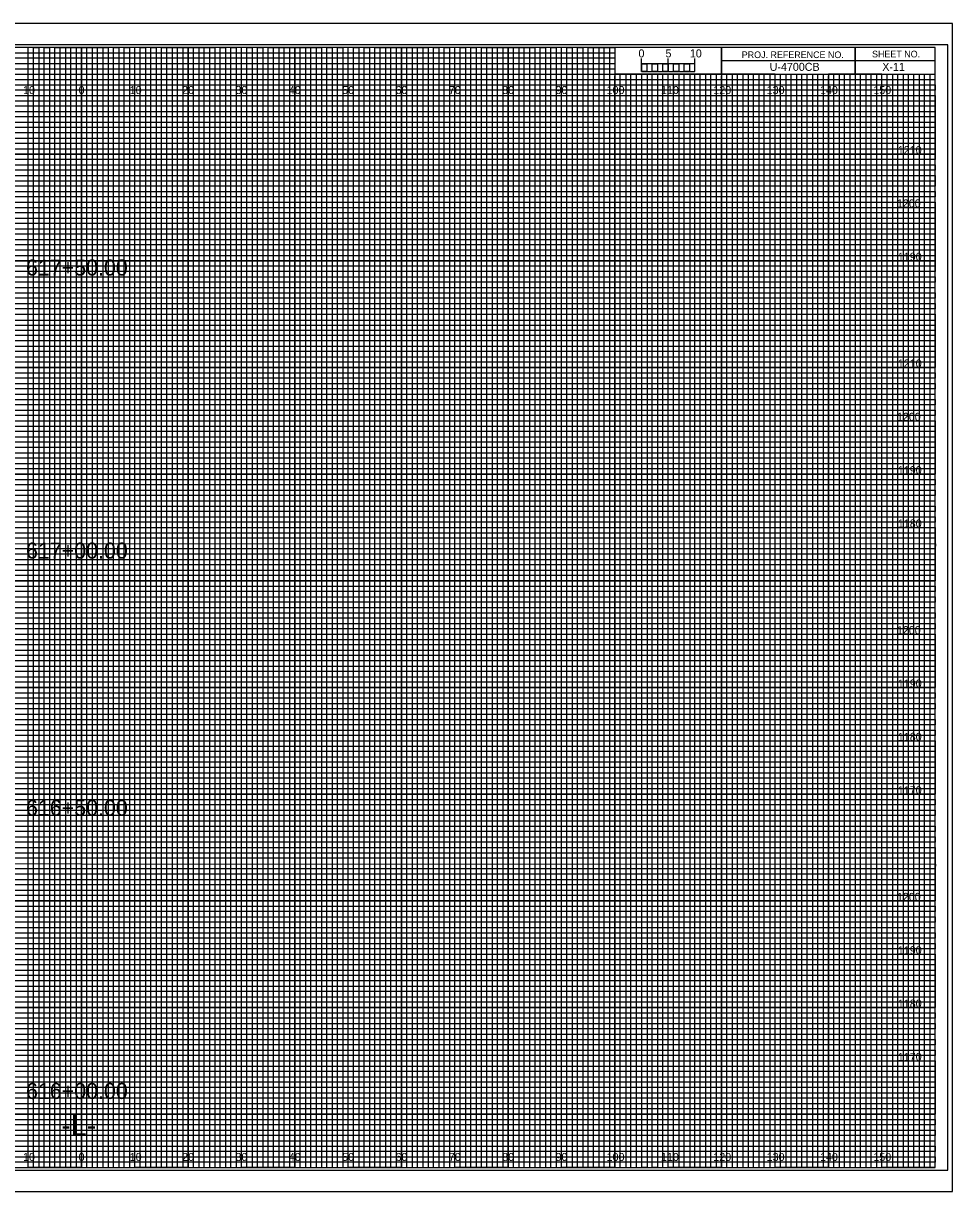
# Model space of a CAD drawing. Extents: x -13 to 323, y 1976 to 2194.
# Drawn here: x 149.1 to 323.3, y 1975.5 to 2194.5 of the extents above; entities that cross this region are included whole.
import ezdxf

# ---------------------------------------------------------------- set-up
doc = ezdxf.new("R2010")
doc.units = 0
for name, color, linetype in [('Prop XS Alignment Label', 7, 'Continuous'), ('Prop XS Bar Scale Labels', 7, 'Continuous'), ('Prop XS Elevation Labels', 7, 'Continuous'), ('Prop XS Offset Labels', 7, 'Continuous'), ('Prop XS Project Number', 7, 'Continuous'), ('Prop XS Sheet Number', 7, 'Continuous'), ('Prop XS Station Labels', 7, 'Continuous'), ('Sheet Cross Section CELL', 7, 'Continuous'), ('Sheet Cross Section Grid Major CELL', 7, 'Continuous'), ('Sheet Cross Section Grid Middle CELL', 7, 'Continuous'), ('Sheet Cross Section Grid Minor 1 CELL', 7, 'Continuous'), ('Sheet Cross Section Grid Minor 2 CELL', 7, 'Continuous'), ('Sheet Cross Section Scale CELL', 7, 'Continuous'), ('Sheet Cutting Line CELL', 7, 'Continuous'), ('Sheet DOT Grid CELL', 7, 'Continuous'), ('Sheet Plot Border Inside CELL', 7, 'Continuous'), ('Sheet Plot Border Outside CELL', 7, 'Continuous')]:
    doc.layers.add(name, color=color, linetype=linetype)

msp = doc.modelspace()

# ---------------------------------------------------------------- linework, layer by layer
at = {"layer": 'Sheet Cross Section CELL'}
for p, q in [((305, 2190), (305, 2185)), ((305, 2185), (305, 2190)), ((280, 2187.5), (280, 2185)), ((320, 2187.49), (280, 2187.49)), ((280, 2185), (320, 2185))]:
    msp.add_line(p, q, dxfattribs=at)
for points in [[(320, 2190), (0, 2190), (0, 1980), (320, 1980)], [(280, 2190), (260, 2190), (260, 2185.03), (280, 2185.03)], [(320, 2190), (280, 2190), (280, 2185), (320, 2185)]]:
    msp.add_lwpolyline(points, close=True, dxfattribs=at)
at = {"layer": 'Sheet Cross Section Grid Major CELL'}
for p, q in [((150, 2190), (140, 2190)), ((150, 1980), (150, 2190)), ((170, 2190), (160, 2190)), ((160, 2190), (160, 1980)), ((170, 1980), (170, 2190)), ((190, 2190), (180, 2190)), ((180, 2190), (180, 1980)), ((190, 1980), (190, 2190)), ((210, 2190), (200, 2190)), ((200, 2190), (200, 1980)), ((210, 1980), (210, 2190)), ((230, 2190), (220, 2190)), ((220, 2190), (220, 1980)), ((230, 1980), (230, 2190)), ((250, 2190), (240, 2190)), ((240, 2190), (240, 1980)), ((250, 1980), (250, 2190)), ((260, 2190), (260, 1980)), ((270, 1980), (270, 2185)), ((290, 2185), (280, 2185)), ((280, 2185), (280, 1980)), ((290, 1980), (290, 2185)), ((310, 2185), (300, 2185)), ((300, 2185), (300, 1980)), ((310, 1980), (310, 2185)), ((160, 1980), (150, 1980)), ((180, 1980), (170, 1980)), ((200, 1980), (190, 1980)), ((220, 1980), (210, 1980)), ((240, 1980), (230, 1980)), ((260, 1980), (250, 1980)), ((280, 1980), (270, 1980)), ((300, 1980), (290, 1980)), ((320, 1980), (310, 1980)), ((320, 1980), (320, 1980))]:
    msp.add_line(p, q, dxfattribs=at)
for points in [[(0, 2180), (320, 2180), (320, 2170), (0, 2170)], [(0, 2160), (320, 2160), (320, 2150), (0, 2150)], [(0, 2140), (320, 2140), (320, 2130), (0, 2130)], [(0, 2120), (320, 2120), (320, 2110), (0, 2110)], [(0, 2100), (320, 2100), (320, 2090), (0, 2090)], [(0, 2080), (320, 2080), (320, 2070), (0, 2070)], [(0, 2060), (320, 2060), (320, 2050), (0, 2050)], [(0, 2040), (320, 2040), (320, 2030), (0, 2030)], [(0, 2020), (320, 2020), (320, 2010), (0, 2010)], [(0, 2000), (320, 2000), (320, 1990), (0, 1990)]]:
    msp.add_lwpolyline(points, dxfattribs=at)
at = {"layer": 'Sheet Cross Section Grid Middle CELL'}
for points in [[(145, 1980), (155, 1980), (155, 2190), (165, 2190), (165, 1980), (175, 1980), (175, 2190), (185, 2190), (185, 1980), (195, 1980), (195, 2190), (205, 2190), (205, 1980), (215, 1980), (215, 2190), (225, 2190), (225, 1980), (235, 1980), (235, 2190), (245, 2190), (245, 1980), (255, 1980), (255, 2190), (259.93, 2190), (260, 2190), (260, 2185), (264.99, 2185), (264.99, 1980), (275, 1980), (275, 2185), (285, 2185), (285, 1980), (295, 1980), (295, 2185), (305, 2185), (305, 1980), (315, 1980), (315, 2185)], [(0, 2185), (275, 2185)], [(0, 2165), (320, 2165), (320, 2175), (0, 2175)], [(0, 2145), (320, 2145), (320, 2155), (0, 2155)], [(0, 2125), (320, 2125), (320, 2135), (0, 2135)], [(0, 2105), (320, 2105), (320, 2115), (0, 2115)], [(0, 2085), (320, 2085), (320, 2095), (0, 2095)], [(0, 2065), (320, 2065), (320, 2075), (0, 2075)], [(0, 2045), (320, 2045), (320, 2055), (0, 2055)], [(0, 2025), (320, 2025), (320, 2035), (0, 2035)], [(0, 2005), (320, 2005), (320, 2015), (0, 2015)], [(0, 1985), (320, 1985), (320, 1995), (0, 1995)]]:
    msp.add_lwpolyline(points, dxfattribs=at)
at = {"layer": 'Sheet Cross Section Grid Minor 1 CELL'}
for p, q in [((0, 2189), (260, 2189)), ((260, 2187.98), (0, 2187.98)), ((260, 2189), (260, 2187.98)), ((0, 2187), (260, 2187)), ((260, 2185.89), (0, 2185.89)), ((260, 2187), (260, 2185.89)), ((0, 2184), (320, 2184))]:
    msp.add_line(p, q, dxfattribs=at)
for points in [[(0, 2183), (270, 2183), (320, 2183), (320, 2182), (0, 2182)], [(0, 2181), (320, 2181), (320, 2179), (0, 2179)], [(0, 2178), (320, 2178), (320, 2177), (0, 2176.98)], [(0, 2176), (320, 2176), (320, 2174), (0, 2174)], [(0, 2173), (320, 2173), (320, 2172), (0, 2172)], [(0, 2171), (320, 2171), (320, 2169), (0, 2169)], [(0, 2168), (320, 2168), (320, 2167), (0, 2167)], [(0, 2166), (320, 2166), (320, 2164), (0, 2164)], [(0, 2163), (320, 2163), (320, 2162), (0, 2162)], [(0, 2161), (320, 2161), (320, 2159), (0, 2159)], [(0, 2158), (320, 2158), (320, 2157), (0, 2157)], [(0, 2156), (320, 2156), (320, 2153.95), (320, 2153), (320, 2152), (0, 2152)], [(0, 2154), (320, 2154), (320, 2153), (0, 2153)], [(0, 2151), (320, 2151), (320, 2149), (0, 2149.03)], [(0, 2149.03), (320, 2149), (320, 2148), (0, 2148)], [(0, 2147), (320, 2147), (320, 2146), (0, 2146)], [(0, 2144), (320, 2144), (320, 2143), (0, 2143)], [(0, 2142), (320, 2142), (320, 2141), (0, 2141)], [(-0.07, 2138.89), (320, 2138.89), (320, 2137.88), (-0.07, 2137.88)], [(0, 2137), (320, 2137), (320, 2136), (0, 2136)], [(0, 2134), (320, 2134), (320, 2133), (0, 2133)], [(0, 2132), (320, 2132), (320, 2131), (0, 2131)], [(0, 2129), (320, 2129), (320, 2128), (0, 2128)], [(0, 2127), (320, 2127), (320, 2126), (0, 2126)], [(0, 2124), (320, 2124), (320, 2123), (0, 2123)], [(0, 2122), (320, 2122), (320, 2121), (0, 2121)], [(0, 2119), (320, 2119), (319.99, 2117.98), (0, 2118)], [(0, 2117), (320, 2117), (320, 2116), (0, 2116)], [(0, 2114), (320, 2114), (320, 2113), (0, 2113)], [(0, 2112), (320, 2112), (320, 2111), (0, 2111)], [(0, 2109), (320, 2109), (320, 2108), (0, 2108)], [(0, 2107), (320, 2107), (320, 2106), (0, 2106)], [(0, 2104), (320, 2104), (320, 2103), (0, 2103)], [(0, 2102), (320, 2102), (320, 2101), (0, 2101)], [(0, 2099), (320, 2099), (320, 2098), (0, 2098)], [(0, 2096.99), (320.07, 2096.91), (320, 2096), (0, 2096)], [(0, 2094), (320, 2094), (320, 2093), (0, 2093)], [(0, 2092), (320, 2092), (320, 2091), (0, 2091)], [(0, 2089), (320, 2089), (320, 2088), (0, 2088)], [(0, 2087), (320, 2087), (320, 2086), (0, 2086)], [(0, 2084), (320, 2084), (320, 2083), (0, 2083)], [(0, 2082), (320, 2082), (320, 2081), (0, 2081)], [(0, 2079), (320, 2079), (320, 2078), (0, 2078)], [(0, 2077), (320, 2077), (320, 2076), (0, 2076)], [(0, 2074), (320, 2074), (320, 2073), (0, 2073)], [(0, 2072), (320, 2072), (320, 2071), (0, 2071)], [(0, 2069), (320, 2069), (320, 2068), (0, 2068)], [(0, 2067), (320, 2067), (320, 2066), (0, 2066)], [(0, 2064), (320, 2064), (320, 2063), (0, 2063)], [(0, 2062), (320, 2062), (320, 2061), (0, 2061)], [(0, 2059), (320, 2059), (319.99, 2057.98), (0, 2058)], [(0, 2057), (320, 2057), (320, 2056), (0, 2056)], [(0, 2054), (320, 2054), (320, 2053), (0, 2053)], [(0, 2052), (320, 2052), (320, 2051), (0, 2051)], [(0, 2049), (320, 2049), (320, 2048), (0, 2048)], [(0, 2047), (320, 2047), (320, 2046), (0, 2046)], [(0, 2044), (320, 2044), (320, 2043), (0, 2043)], [(0, 2042), (320, 2042), (320, 2041), (0, 2041)], [(0, 2039), (320, 2039), (320, 2038), (0, 2038)], [(0, 2036.99), (320.07, 2036.91), (320, 2036), (0, 2036)], [(0, 2034), (320, 2034), (320, 2033), (0, 2033)], [(0, 2032), (320, 2032), (320, 2031), (0, 2031)], [(0, 2029), (320, 2029), (320, 2028), (0, 2028)], [(0, 2027), (320, 2027), (320, 2026), (0, 2026)], [(0, 2024), (320, 2024), (320, 2023), (0, 2023)], [(0, 2022), (320, 2022), (320, 2021), (0, 2021)], [(0, 2019), (320, 2019), (320, 2018), (0, 2018)], [(0, 2017), (320, 2017), (320, 2016), (0, 2016)], [(0, 2014), (320, 2014), (320, 2013), (0, 2013)], [(0, 2012), (320, 2012), (320, 2011), (0, 2011)], [(0, 2009), (320, 2009), (320, 2008), (0, 2008)], [(0, 2007), (320, 2007), (320, 2006), (0, 2006)], [(0, 2004), (320, 2004), (320, 2003), (0, 2003)], [(0, 2002), (320, 2002), (320, 2001), (0, 2001)], [(0, 1999), (320, 1999), (320, 1998), (0, 1998)], [(0, 1997), (320, 1997), (320, 1996), (0, 1996)], [(0, 1994), (320, 1994), (320, 1993), (0, 1993)], [(0, 1992), (320, 1992), (320, 1991), (0, 1991)], [(0, 1989), (320, 1989), (320, 1988), (0, 1988)], [(0, 1987), (320, 1987), (320, 1986), (0, 1986)], [(0, 1984), (320, 1984), (320, 1983), (0, 1983)], [(0, 1982), (320, 1982), (320, 1981), (0, 1981)]]:
    msp.add_lwpolyline(points, dxfattribs=at)
at = {"layer": 'Sheet Cross Section Grid Minor 2 CELL'}
for p, q in [((267, 2185), (266.01, 2185)), ((266.01, 2185), (266.01, 1980)), ((267, 1980), (267, 2185)), ((269, 2185), (268, 2185)), ((268, 2185), (268, 1980)), ((269, 1980), (269, 2185)), ((266.01, 1980), (265, 1980)), ((268, 1980), (267, 1980))]:
    msp.add_line(p, q, dxfattribs=at)
for points in [[(150, 1980), (151, 1980), (151, 2190), (152, 2190), (152, 1980)], [(152, 1980), (153, 1980), (153, 2190), (154, 2190), (154, 1980)], [(155, 1980), (156, 1980), (156, 2190), (157, 2190), (157, 1980)], [(157, 1980), (158, 1980), (158, 2190), (159, 2190), (159, 1980)], [(160, 1980), (161, 1980), (161, 2190), (162, 2190), (162, 1980)], [(162, 1980), (163, 1980), (163, 2190), (164, 2190), (164, 1980)], [(165, 1980), (166, 1980), (166, 2190), (167, 2190), (167, 1980)], [(167, 1980), (168, 1980), (168, 2190), (169, 2190), (169, 1980)], [(170, 1980), (171, 1980), (171, 2190), (172, 2190), (172, 1980)], [(172, 1980), (173, 1980), (173, 2190), (174, 2190), (174, 1980)], [(175, 1980), (176, 1980), (176, 2190), (177, 2190), (177, 1980)], [(177, 1980), (178, 1980), (178, 2190), (179, 2190), (179, 1980)], [(180, 1980), (181, 1980), (181, 2190), (182, 2190), (182, 1980)], [(182, 1980), (183, 1980), (183, 2190), (184, 2190), (184, 1980)], [(185, 1980), (186, 1980), (186, 2190), (187, 2190), (187, 1980)], [(187, 1980), (188, 1980), (188, 2190), (189, 2190), (189, 1980)], [(190, 1980), (191, 1980), (191, 2190), (192, 2190), (192, 1980)], [(192, 1980), (193, 1980), (193, 2190), (194, 2190), (194, 1980)], [(195, 1980), (196, 1980), (196, 2190), (197, 2190), (197, 1980)], [(197, 1980), (198, 1980), (198, 2190), (199, 2190), (199, 1980)], [(200, 1980), (201, 1980), (201, 2190), (202, 2190), (202, 1980)], [(202, 1980), (203, 1980), (203, 2190), (204, 2190), (204, 1980)], [(205, 1980), (206, 1980), (206, 2190), (207, 2190), (207, 1980)], [(207, 1980), (208, 1980), (208, 2190), (209, 2190), (209, 1980)], [(210, 1980), (211, 1980), (211, 2190), (212, 2190), (212, 1980)], [(212, 1980), (213, 1980), (213, 2190), (214, 2190), (214, 1980)], [(215, 1980), (216, 1980), (216, 2190), (217, 2190), (217, 1980)], [(217, 1980), (218, 1980), (218, 2190), (219, 2190), (219, 1980)], [(220, 1980), (221, 1980), (221, 2190), (222, 2190), (222, 1980)], [(222, 1980), (223, 1980), (223, 2190), (224, 2190), (224, 1980)], [(225, 1980), (226, 1980), (226, 2190), (227, 2190), (227, 1980)], [(227, 1980), (228, 1980), (228, 2190), (229, 2190), (229, 1980)], [(230, 1980), (231, 1980), (231, 2190), (232, 2190), (232, 1980)], [(232, 1980), (233, 1980), (233, 2190), (234, 2190), (234, 1980)], [(235, 1980), (236, 1980), (236, 2190), (237, 2190), (237, 1980)], [(237, 1980), (238, 1980), (238, 2190), (239, 2190), (239, 1980)], [(240, 1980), (241, 1980), (241, 2190), (242, 2190), (242, 1980)], [(242, 1980), (243, 1980), (243, 2190), (244, 2190), (244, 1980)], [(245, 1980), (246, 1980), (246, 2190), (247, 2190), (247, 1980)], [(247, 1980), (248, 1980), (248, 2190), (249, 2190), (249, 1980)], [(250, 1980), (251, 1980), (251, 2190), (252, 2190), (252, 1980)], [(252, 1980), (253, 1980), (253, 2190), (254, 2190), (254, 1980)], [(255, 1980), (256, 1980), (256, 2190), (257, 2190), (257, 1980)], [(257, 1980), (258, 1980), (258, 2190), (259, 2190), (259, 1980)], [(260, 1980), (261, 1980), (261, 2185), (262.02, 2185), (262.02, 1980)], [(262, 1980), (263, 1980), (263, 2185), (263.99, 2185), (263.99, 1980)], [(270, 1980), (270.98, 1980), (270.98, 2185), (272, 2185), (272, 1980)], [(272, 1980), (273, 1980), (273, 2185), (274.05, 2185), (274.05, 1980)], [(275, 1980), (276, 1980), (276, 2185), (277, 2185), (277, 1980)], [(277, 1980), (278, 1980), (278, 2185), (279, 2185), (279, 1980)], [(280, 1980), (281, 1980), (281, 2185), (282, 2185), (282, 1980)], [(282, 1980), (283, 1980), (283, 2185), (284, 2185), (284, 1980)], [(285, 1980), (286, 1980), (286, 2185), (287, 2185), (287, 1980)], [(287, 1980), (288, 1980), (288, 2185), (289, 2185), (289, 1980)], [(290, 1980), (291, 1980), (291, 2185), (292, 2185), (292, 1980)], [(292, 1980), (293, 1980), (293, 2185), (294, 2185), (294, 1980)], [(295, 1980), (296, 1980), (296, 2185), (297, 2185), (297, 1980)], [(297, 1980), (298, 1980), (298, 2185), (299, 2185), (299, 1980)], [(300, 1980), (301, 1980), (301, 2185), (302, 2185), (302, 1980)], [(302, 1980), (303, 1980), (303, 2185), (304, 2185), (304, 1980)], [(305, 1980), (306, 1980), (306, 2185), (307, 2185), (307, 1980)], [(307, 1980), (308, 1980), (308, 2185), (309, 2185), (309, 1980)], [(310, 1980), (311, 1980), (311, 2185), (312, 2185), (312, 1980)], [(312, 1980), (313, 1980), (313, 2185), (314, 2185), (314, 1980)], [(315, 1980), (316, 1980), (316, 2185), (317, 2185), (317, 1980)], [(317, 1980), (318, 1980), (318, 2185), (319, 2185), (319, 1980)]]:
    msp.add_lwpolyline(points, dxfattribs=at)
at = {"layer": 'Sheet Cross Section Scale CELL'}
for p, q in [((265, 2185.49), (265, 2187.9)), ((265, 2186.9), (265, 2187.9)), ((270, 2185.49), (270, 2187.9)), ((275, 2185.49), (275, 2187.9)), ((275, 2186.9), (275, 2187.9))]:
    msp.add_line(p, q, dxfattribs=at)
for points in [[(275, 2186.9), (265, 2186.9), (265, 2185.49), (275, 2185.49)], [(265, 2186.9), (266, 2186.9), (266, 2185.49), (265, 2185.49)], [(267, 2186.9), (268, 2186.9), (268, 2185.49), (267, 2185.49)], [(269, 2186.9), (270, 2186.9), (270, 2185.49), (269, 2185.49)], [(271, 2186.9), (272, 2186.9), (272, 2185.49), (271, 2185.49)], [(273, 2186.9), (274, 2186.9), (274, 2185.49), (273, 2185.49)]]:
    msp.add_lwpolyline(points, close=True, dxfattribs=at)
at = {"layer": 'Sheet Cutting Line CELL'}
for p, q in [((323.3, 2194.5), (-13.4, 2194.5)), ((-13.4, 1975.5), (323.3, 1975.5))]:
    msp.add_line(p, q, dxfattribs=at)
at = {"layer": 'Sheet DOT Grid CELL'}
for p, q in [((150, 1980), (150, 2190)), ((160, 1980), (160, 2190)), ((170, 1980), (170, 2190)), ((180, 1980), (180, 2190)), ((190, 1980), (190, 2190)), ((200, 1980), (200, 2190)), ((210, 1980), (210, 2190)), ((220, 1980), (220, 2190)), ((230, 1980), (230, 2190)), ((240, 1980), (240, 2190)), ((250, 1980), (250, 2190)), ((260, 1980), (260, 2184.69)), ((270, 1980), (270, 2184.69)), ((280, 1980), (280, 2184.69)), ((290, 1980), (290, 2184.69)), ((300, 1980), (300, 2184.69)), ((310, 1980), (310, 2184.69)), ((0, 2180), (320, 2180)), ((0, 2170), (320, 2170)), ((0, 2160), (320, 2160)), ((0, 2150), (320, 2150)), ((0, 2140), (320, 2140)), ((0, 2130), (320, 2130)), ((0, 2120), (320, 2120)), ((0, 2110), (320, 2110)), ((0, 2100), (320, 2100)), ((0, 2090), (320, 2090)), ((0, 2080), (320, 2080)), ((0, 2070), (320, 2070)), ((0, 2060), (320, 2060)), ((0, 2050), (320, 2050)), ((0, 2040), (320, 2040)), ((0, 2030), (320, 2030)), ((0, 2020), (320, 2020)), ((0, 2010), (320, 2010)), ((0, 2000), (320, 2000)), ((0, 1990), (320, 1990))]:
    msp.add_line(p, q, dxfattribs=at)
at = {"layer": 'Sheet Plot Border Inside CELL'}
msp.add_lwpolyline([(-10.8, 1979.5), (322.4, 1979.5), (322.4, 2190.5), (-10.8, 2190.5)], close=True, dxfattribs=at)
at = {"layer": 'Sheet Plot Border Outside CELL'}
msp.add_lwpolyline([(-13.4, 1975.5), (323.3, 1975.5), (323.3, 2194.5), (-13.4, 2194.5)], close=True, dxfattribs=at)

# ---------------------------------------------------------------- texts
at = {"layer": 'Prop XS Alignment Label'}
msp.add_text('-L-', height=4, dxfattribs=at).set_placement((156.2, 1986))
at = {"layer": 'Prop XS Bar Scale Labels'}
for s, p in [('5', (269.47, 2188.12)), ('10', (274.04, 2188.12))]:
    msp.add_text(s, height=1.5, dxfattribs=at).set_placement(p)
at = {"layer": 'Prop XS Elevation Labels'}
for s, p in [('1210', (313.03, 2170)), ('1200', (312.85, 2160)), ('1190', (313.03, 2150)), ('1210', (313.03, 2130)), ('1200', (312.85, 2120)), ('1190', (313.03, 2110)), ('1180', (313.03, 2100)), ('1200', (312.85, 2080)), ('1190', (313.03, 2070)), ('1180', (313.03, 2060)), ('1170', (313.03, 2050)), ('1200', (312.85, 2030)), ('1190', (313.03, 2020)), ('1180', (313.03, 2010)), ('1170', (313.03, 2000))]:
    msp.add_text(s, height=1.5, dxfattribs=at).set_placement(p)
at = {"layer": 'Prop XS Offset Labels'}
for s, p in [('10', (149.04, 2181.25)), ('0', (159.45, 2181.25)), ('0', (159.45, 2181.25)), ('10', (169.04, 2181.25)), ('20', (178.86, 2181.25)), ('30', (188.86, 2181.25)), ('40', (198.86, 2181.25)), ('50', (208.86, 2181.25)), ('60', (218.86, 2181.25)), ('70', (228.86, 2181.25)), ('80', (238.86, 2181.25)), ('90', (248.86, 2181.25)), ('100', (258.44, 2181.25)), ('110', (268.62, 2181.25)), ('120', (278.44, 2181.25)), ('130', (288.44, 2181.25)), ('140', (298.44, 2181.25)), ('150', (308.44, 2181.25)), ('10', (149.04, 1981.25)), ('0', (159.45, 1981.25)), ('0', (159.45, 1981.25)), ('10', (169.04, 1981.25)), ('20', (178.86, 1981.25)), ('30', (188.86, 1981.25)), ('40', (198.86, 1981.25)), ('50', (208.86, 1981.25)), ('60', (218.86, 1981.25)), ('70', (228.86, 1981.25)), ('80', (238.86, 1981.25)), ('90', (248.86, 1981.25)), ('100', (258.44, 1981.25)), ('110', (268.62, 1981.25)), ('120', (278.44, 1981.25)), ('130', (288.44, 1981.25)), ('140', (298.44, 1981.25)), ('150', (308.44, 1981.25))]:
    msp.add_text(s, height=1.5, dxfattribs=at).set_placement(p)
at = {"layer": 'Prop XS Project Number'}
msp.add_text('U-4700CB', height=1.5, dxfattribs=at).set_placement((289, 2185.6))
at = {"layer": 'Prop XS Sheet Number'}
msp.add_text('X-11', height=1.5, dxfattribs=at).set_placement((310.11, 2185.6))
at = {"layer": 'Prop XS Station Labels'}
for s, p in [('617+50.00', (149.59, 2147.23)), ('617+00.00', (149.59, 2094.17)), ('616+50.00', (149.59, 2045.96)), ('616+00.00', (149.59, 1992.87))]:
    msp.add_text(s, height=3, dxfattribs=at).set_placement(p)
at = {"layer": 'Sheet Cross Section CELL'}
for s, p in [('PROJ. REFERENCE NO.', (283.77, 2187.99)), ('SHEET NO.', (308.19, 2188.12))]:
    msp.add_text(s, height=1.25, dxfattribs=at).set_placement(p)
at = {"layer": 'Sheet Cross Section Scale CELL'}
msp.add_text('0', height=1.5, dxfattribs=at).set_placement((264.41, 2188.12))

doc.saveas('drawing.dxf')
